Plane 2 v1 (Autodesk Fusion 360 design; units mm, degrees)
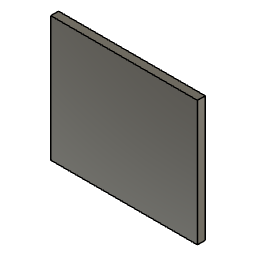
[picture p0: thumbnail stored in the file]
sketch "Sketch1" plane through (0, 0, 0) normal (0, 1, 0) x axis (1, 0, 0)
  line L1 (187.57, 0) -> (0, 0)
  line L2 (187.57, -160) -> (187.57, 0)
  line L3 (0, -160) -> (187.57, -160)
  line L4 (0, 0) -> (0, -160)
  point P1 (0, 0)
  point P2 (0, 0)
  point P3 (187.57, 0)
  point P5 (0, -160)
  horizontal L1
  vertical L2
  horizontal L3
  vertical L4
  coincident P1 P2
  dimension "d1" distance P2 P3 = 187.57
  dimension "d2" distance P2 P5 = 160
extrude "Extrude1" new body sketch "Sketch1" along normal blind 10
